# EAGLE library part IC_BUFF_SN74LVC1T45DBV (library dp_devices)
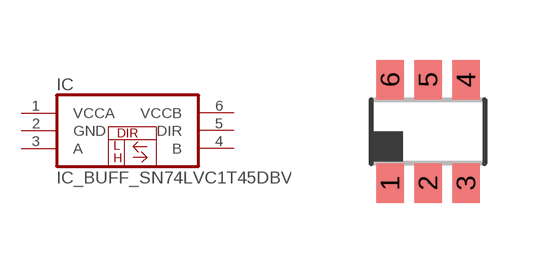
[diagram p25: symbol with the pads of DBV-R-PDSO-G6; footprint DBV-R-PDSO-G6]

Designator prefix IC

## IC_BUFF_SN74LVC1T45DBV  [DBV-R-PDSO-G6]
1  VCCA  pwr
2  GND  pwr
3  A
4  B
5  DIR  in
6  VCCB  pwr

## Footprint DBV-R-PDSO-G6 (pad centres in mm)
smd 0.69 x 0.99: 1 -0.95,-1.29; 2 0,-1.29; 3 0.95,-1.29; 4 0.95,1.3; 5 0,1.3; 6 -0.95,1.3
